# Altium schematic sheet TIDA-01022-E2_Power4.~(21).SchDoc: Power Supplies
size 431 x 279 mm; Date: Not shown in title block; ApprovedBy: Not shown in title block; CheckedBy: Not shown in title block; Author: Not shown in title block; CompanyName: Not shown in title block; DrawnBy: Avinash N; Engineer: Not shown in title block; Organization: Not shown in title block; Address1: Not shown in title block; Address2: Not shown in title block; Address3: Not shown in title block; Address4: Not shown in title block; DocumentNumber: 1; Revision: Use project parameter SCH_Rev; SheetNumber: 24; SheetTotal: 26; PageSetup: Record=PageOptions¦CenterHorizontal=True¦CenterVertical=True¦PrintScale=1.00¦XCorrection=1.00¦YCorrection=1.00¦PrintKind=0¦BorderSize=5000000¦LeftOffset=0¦BottomOffset=0¦Orientation=2¦PaperLength=1000¦PaperWidth=1000¦Scale=100¦PaperSource=15¦PrintQuality=600¦MediaType=1¦DitherType=10¦PaperKind=Letter¦PrintScaleMode=1
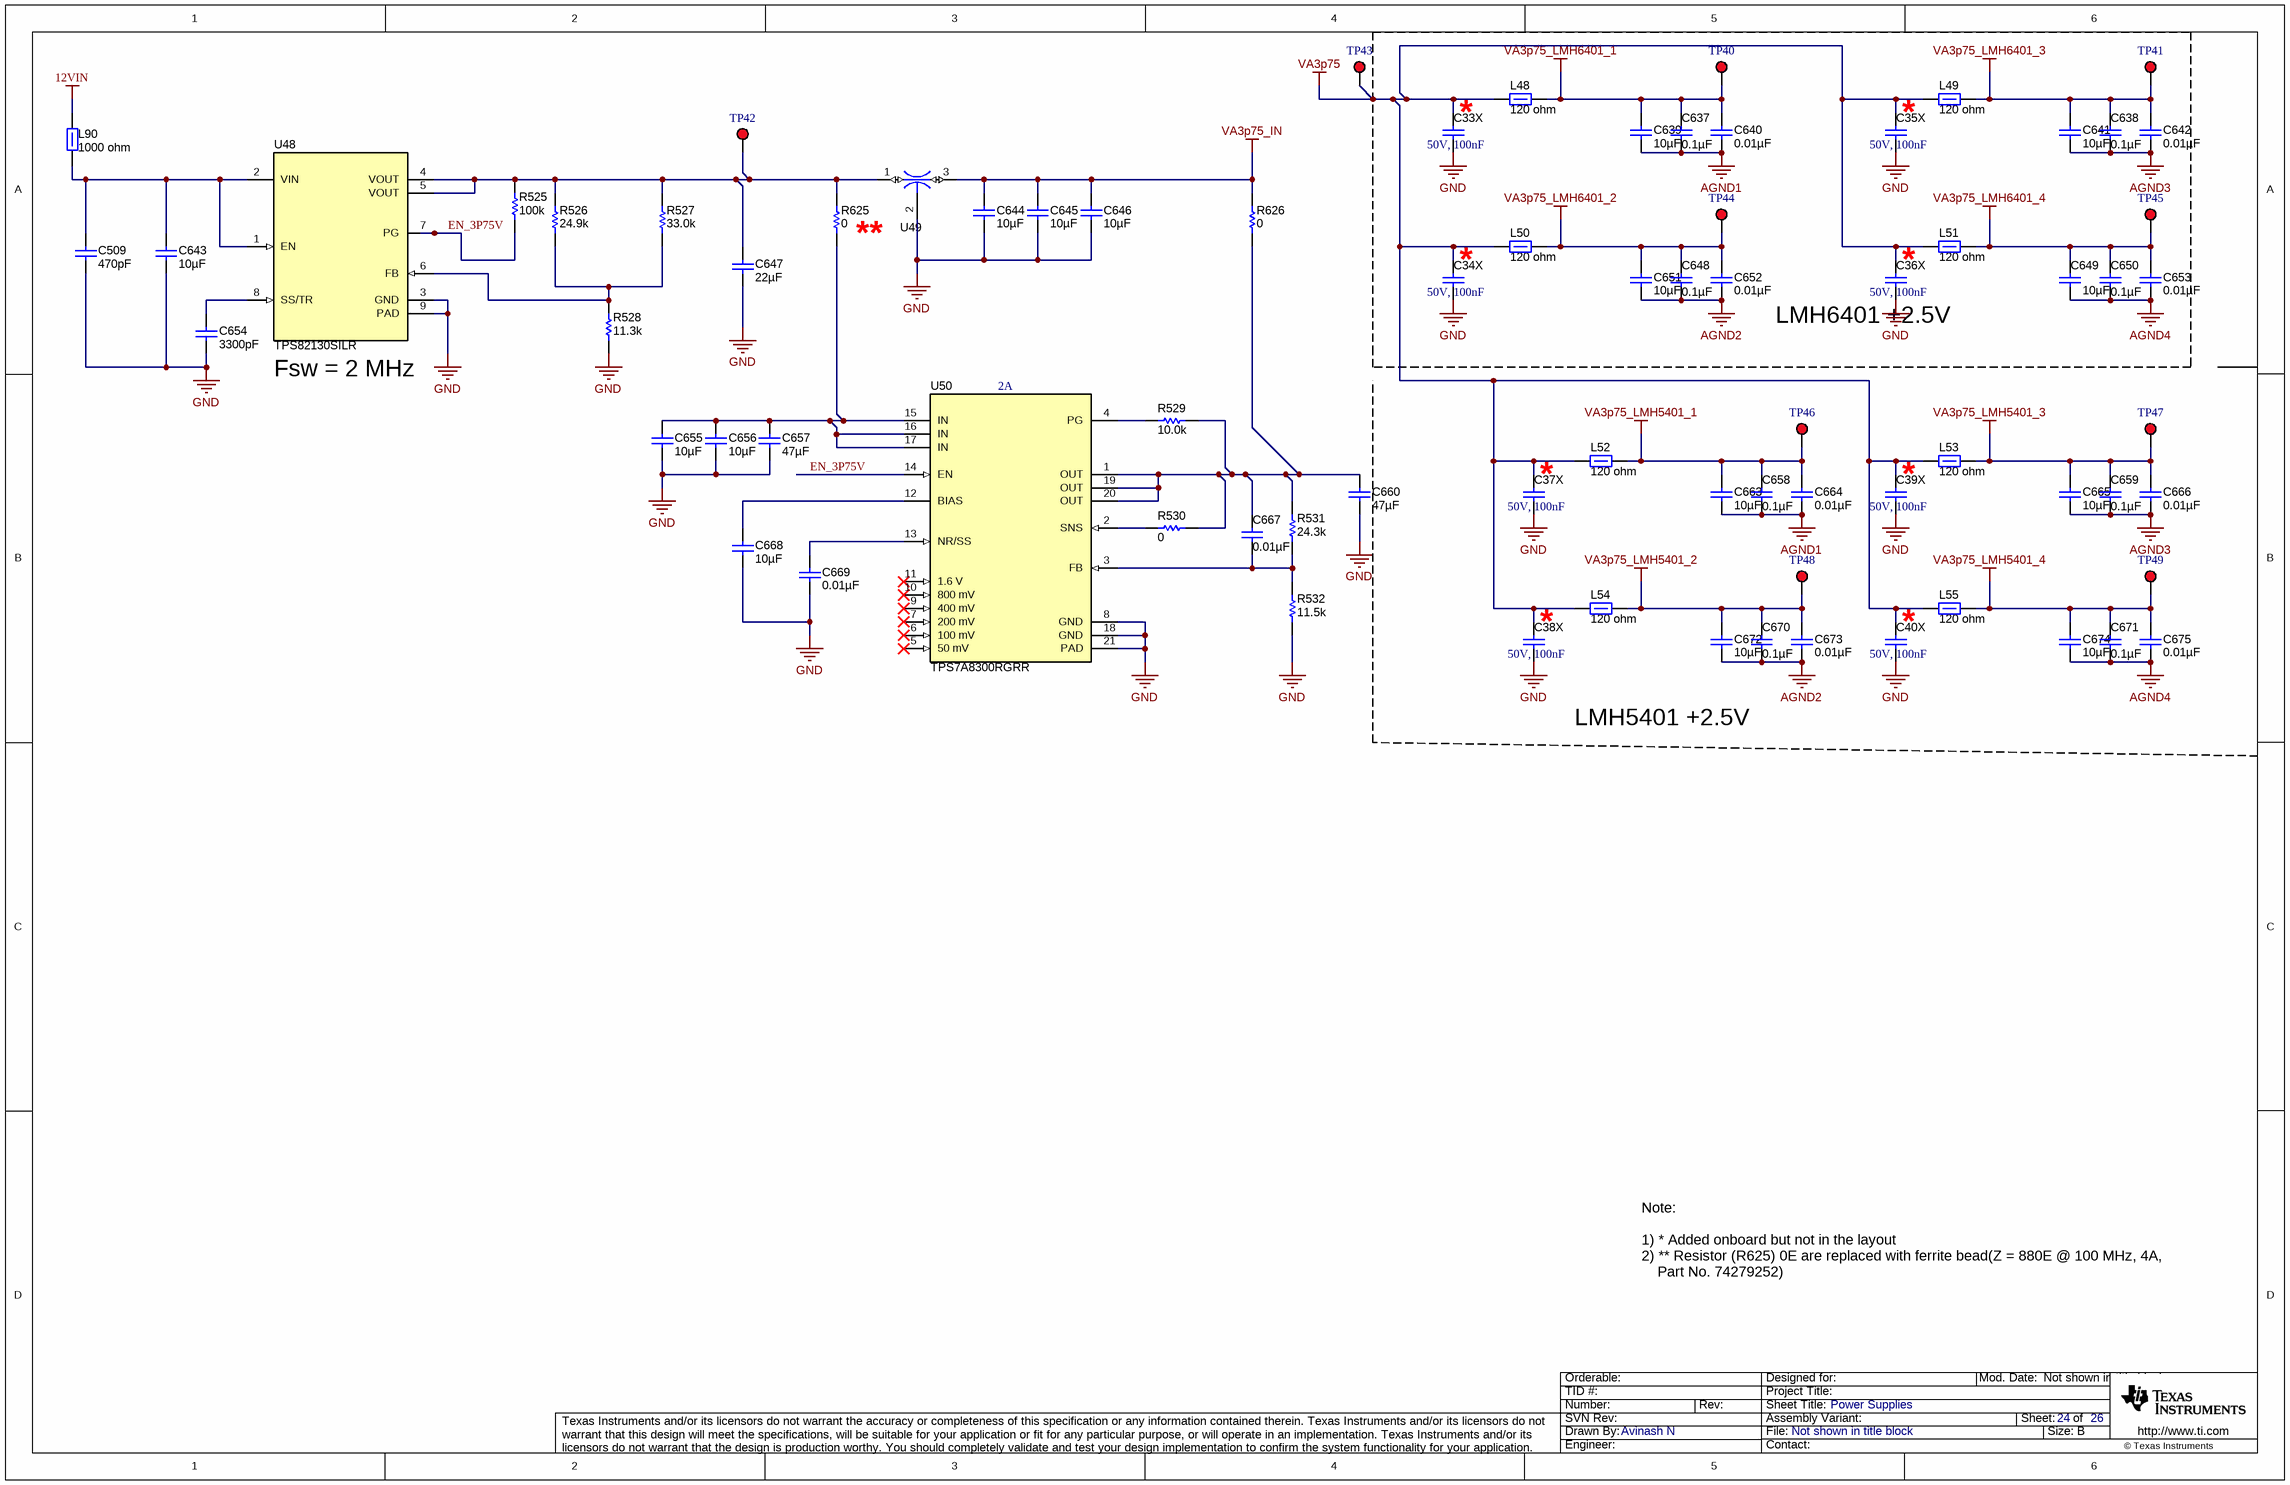
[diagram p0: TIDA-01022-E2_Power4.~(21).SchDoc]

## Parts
C33X  50V, 100nF  [0603_1.6x0.8x0.8mm_Reflow Soldering]
C34X  50V, 100nF  [0603_1.6x0.8x0.8mm_Reflow Soldering]
C35X  50V, 100nF  [0603_1.6x0.8x0.8mm_Reflow Soldering]
C36X  50V, 100nF  [0603_1.6x0.8x0.8mm_Reflow Soldering]
C37X  50V, 100nF  [0603_1.6x0.8x0.8mm_Reflow Soldering]
C38X  50V, 100nF  [0603_1.6x0.8x0.8mm_Reflow Soldering]
C39X  50V, 100nF  [0603_1.6x0.8x0.8mm_Reflow Soldering]
C40X  50V, 100nF  [0603_1.6x0.8x0.8mm_Reflow Soldering]
C509  ValueDisplayed: 470pF  [0402]  (hidden comment: GRM1555C1H471JA01D)
C637  ValueDisplayed: 0.1µF  [0603]  (hidden comment: CGA3E2X7R1H104K080AA)
C638  ValueDisplayed: 0.1µF  [0603]  (hidden comment: CGA3E2X7R1H104K080AA)
C639  ValueDisplayed: 10µF  [1206_190]  (hidden comment: C3216X7R1E106M160AE)
C640  ValueDisplayed: 0.01µF  [0603]  (hidden comment: GCM188R71H103KA37D)
C641  ValueDisplayed: 10µF  [1206_190]  (hidden comment: C3216X7R1E106M160AE)
C642  ValueDisplayed: 0.01µF  [0603]  (hidden comment: GCM188R71H103KA37D)
C643  ValueDisplayed: 10µF  [1206_190]  (hidden comment: C3216X7R1E106M160AE)
C644  ValueDisplayed: 10µF  [1206_190]  (hidden comment: C3216X7R1E106M160AE)
C645  ValueDisplayed: 10µF  [1206_190]  (hidden comment: C3216X7R1E106M160AE)
C646  ValueDisplayed: 10µF  [1206_190]  (hidden comment: C3216X7R1E106M160AE)
C647  ValueDisplayed: 22µF  [0805_HV]  (hidden comment: JMK212BJ226MG-T)
C648  ValueDisplayed: 0.1µF  [0603]  (hidden comment: CGA3E2X7R1H104K080AA)
C649  ValueDisplayed: 10µF  [1206_190]  (hidden comment: C3216X7R1E106M160AE)
C650  ValueDisplayed: 0.1µF  [0603]  (hidden comment: CGA3E2X7R1H104K080AA)
C651  ValueDisplayed: 10µF  [1206_190]  (hidden comment: C3216X7R1E106M160AE)
C652  ValueDisplayed: 0.01µF  [0603]  (hidden comment: GCM188R71H103KA37D)
C653  ValueDisplayed: 0.01µF  [0603]  (hidden comment: GCM188R71H103KA37D)
C654  ValueDisplayed: 3300pF  [0603]  (hidden comment: GRM1885C1H332JA01D)
C655  ValueDisplayed: 10µF  [0805_HV]  (hidden comment: GRM21BR61C106KE15L)
C656  ValueDisplayed: 10µF  [0805_HV]  (hidden comment: GRM21BR61C106KE15L)
C657  ValueDisplayed: 47µF  [0805_HV]  (hidden comment: GRM219R60G476ME44D)
C658  ValueDisplayed: 0.1µF  [0603]  (hidden comment: CGA3E2X7R1H104K080AA)
C659  ValueDisplayed: 0.1µF  [0603]  (hidden comment: CGA3E2X7R1H104K080AA)
C660  ValueDisplayed: 47µF  [0805_HV]  (hidden comment: GRM219R60G476ME44D)
C663  ValueDisplayed: 10µF  [1206_190]  (hidden comment: C3216X7R1E106M160AE)
C664  ValueDisplayed: 0.01µF  [0603]  (hidden comment: GCM188R71H103KA37D)
C665  ValueDisplayed: 10µF  [1206_190]  (hidden comment: C3216X7R1E106M160AE)
C666  ValueDisplayed: 0.01µF  [0603]  (hidden comment: GCM188R71H103KA37D)
C667  ValueDisplayed: 0.01µF  [0603]  (hidden comment: GRM188R71H103KA01D)
C668  ValueDisplayed: 10µF  [0805_HV]  (hidden comment: GRM21BR61C106KE15L)
C669  ValueDisplayed: 0.01µF  [0603]  (hidden comment: GRM188R71H103KA01D)
C670  ValueDisplayed: 0.1µF  [0603]  (hidden comment: CGA3E2X7R1H104K080AA)
C671  ValueDisplayed: 0.1µF  [0603]  (hidden comment: CGA3E2X7R1H104K080AA)
C672  ValueDisplayed: 10µF  [1206_190]  (hidden comment: C3216X7R1E106M160AE)
C673  ValueDisplayed: 0.01µF  [0603]  (hidden comment: GCM188R71H103KA37D)
C674  ValueDisplayed: 10µF  [1206_190]  (hidden comment: C3216X7R1E106M160AE)
C675  ValueDisplayed: 0.01µF  [0603]  (hidden comment: GCM188R71H103KA37D)
L48  ValueDisplayed: 120 ohm  [0603]  (hidden comment: BLM18SG121TN1D)
L49  ValueDisplayed: 120 ohm  [0603]  (hidden comment: BLM18SG121TN1D)
L50  ValueDisplayed: 120 ohm  [0603]  (hidden comment: BLM18SG121TN1D)
L51  ValueDisplayed: 120 ohm  [0603]  (hidden comment: BLM18SG121TN1D)
L52  ValueDisplayed: 120 ohm  [0603]  (hidden comment: BLM18SG121TN1D)
L53  ValueDisplayed: 120 ohm  [0603]  (hidden comment: BLM18SG121TN1D)
L54  ValueDisplayed: 120 ohm  [0603]  (hidden comment: BLM18SG121TN1D)
L55  ValueDisplayed: 120 ohm  [0603]  (hidden comment: BLM18SG121TN1D)
L90  ValueDisplayed: 1000 ohm  [1806_HighSpeed]  (hidden comment: BLM41PG102SN1L)
R525  ValueDisplayed: 100k  [0402]  (hidden comment: CRCW0402100KFKED)
R526  ValueDisplayed: 24.9k  [0603]  (hidden comment: CRCW060324K9FKEA)
R527  ValueDisplayed: 33.0k  [0402]  (hidden comment: ERA-2AEB333X)
R528  ValueDisplayed: 11.3k  [0402]  (hidden comment: CRCW040211K3FKED)
R529  ValueDisplayed: 10.0k  [0603]  (hidden comment: CRCW060310K0FKEA)
R530  ValueDisplayed: 0  [0603]  (hidden comment: CRCW06030000Z0EA)
R531  ValueDisplayed: 24.3k  [0603]  (hidden comment: CRCW060324K3FKEA)
R532  ValueDisplayed: 11.5k  [0603]  (hidden comment: CRCW060311K5FKEA)
R625  ValueDisplayed: 0  [1206]  (hidden comment: CRCW12060000Z0EA)
R626  ValueDisplayed: 0  [1206]  (hidden comment: CRCW12060000Z0EA)
TP40  5000  [Keystone5000]  (value not drawn)
TP41  5000  [Keystone5000]  (value not drawn)
TP42  5000  [Keystone5000]  (value not drawn)
TP43  5000  [Keystone5000]  (value not drawn)
TP44  5000  [Keystone5000]  (value not drawn)
TP45  5000  [Keystone5000]  (value not drawn)
TP46  5000  [Keystone5000]  (value not drawn)
TP47  5000  [Keystone5000]  (value not drawn)
TP48  5000  [Keystone5000]  (value not drawn)
TP49  5000  [Keystone5000]  (value not drawn)
U48  TPS82130SILR  [SIL0008D_SMD]
U49  NFM31PC276B0J3L  [Murata_NFM31P]  (value not drawn)
U50  TPS7A8300RGRR  [RGR0020A]

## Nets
12VIN: L90.2
AGND1: C637.2 C639.1 C640.2 C658.2 C663.1 C664.2
AGND2: C648.2 C651.1 C652.2 C670.2 C672.1 C673.2
AGND3: C638.2 C641.1 C642.2 C659.2 C665.1 C666.2
AGND4: C649.1 C650.2 C653.2 C671.2 C674.1 C675.2
GND: C33X.1 C34X.1 C35X.1 C36X.1 C37X.1 C38X.1 C39X.1 C40X.1 C509.2 C643.2 C644.1 C645.1 C646.1 C647.2 C654.1 C655.2 C656.2 C657.2 C660.2 C668.2 C669.2 R528.1 R532.1 U48.3(GND) U48.9(PAD) U49.2 U50.8(GND) U50.18(GND) U50.21(PAD)
VA3p75: C33X.2 C34X.2 C35X.2 C36X.2 C37X.2 C38X.2 C39X.2 C40X.2 L48.1 L49.1 L50.1 L51.1 L52.1 L53.1 L54.1 L55.1 TP43.1
VA3p75_IN: C644.2 C645.2 C646.2 R626.2 U49.3
VA3p75_LMH5401_1: C658.1 C663.2 C664.1 L52.2 TP46.1
VA3p75_LMH5401_2: C670.1 C672.2 C673.1 L54.2 TP48.1
VA3p75_LMH5401_3: C659.1 C665.2 C666.1 L53.2 TP47.1
VA3p75_LMH5401_4: C671.1 C674.2 C675.1 L55.2 TP49.1
VA3p75_LMH6401_1: C637.1 C639.2 C640.1 L48.2 TP40.1
VA3p75_LMH6401_2: C648.1 C651.2 C652.1 L50.2 TP44.1
VA3p75_LMH6401_3: C638.1 C641.2 C642.1 L49.2 TP41.1
VA3p75_LMH6401_4: C649.2 C650.1 C653.1 L51.2 TP45.1
EN_3P75V: R525.1 U48.7(PG) U50.14(EN)
NetC509_1: C509.1 C643.1 L90.1 U48.1(EN) U48.2(VIN)
NetC647_1: C647.1 R525.2 R526.2 R527.2 R625.2 TP42.1 U48.4(VOUT) U48.5(VOUT) U49.1
NetC654_2: C654.2 U48.8(SS/TR)
NetC655_1: C655.1 C656.1 C657.1 R625.1 U50.15(IN) U50.16(IN) U50.17(IN)
NetC660_1: C660.1 C667.1 R529.1 R530.2 R531.2 R626.1 U50.1(OUT) U50.19(OUT) U50.20(OUT)
NetC667_2: C667.2 R531.1 R532.2 U50.3(FB)
NetC668_1: C668.1 U50.12(BIAS)
NetC669_1: C669.1 U50.13(NR/SS)
NetR526_1: R526.1 R527.1 R528.2 U48.6(FB)
NetR529_2: R529.2 U50.4(PG)
NetR530_1: R530.1 U50.2(SNS)

Not connected (* = marked no-connect by the designer): U50 5(50_mV)* 6(100_mV)* 7(200_mV)* 9(400_mV)* 10(800_mV)* 11(1.6_V)*

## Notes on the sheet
- (near C33X) *
- (near C35X) *
- (near R625) *
- *
- (near C34X) *
- (near C36X) *
- (near C36X) LMH6401 +2.5V
- (near U48) Fsw = 2 MHz
- (near U50) 2A
- (near C37X) *
- (near C39X) *
- (near C38X) *
- (near C40X) *
- LMH5401 +2.5V
- Note:
  1) * Added onboard but not in the layout
  2) ** Resistor (R625) 0E are replaced with ferrite bead(Z = 880E @ 100 MHz, 4A,
  Part No. 74279252)

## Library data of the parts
C33X C34X C35X C36X C37X C38X C39X C40X = 885012206095: WCAP-CSGP Ceramic Capacitors, 0603, X7R, 50V, 100nF; Rated Voltage: 50V DC
C509 = GRM1555C1H471JA01D: CAP, CERM, 470 pF, 50 V, +/- 5%, C0G/NP0, 0402; Manufacturer: MuRata; Polarized: N; CompType: Capacitor; Value: 470pF; U/M: EA; Cap_F: 0.00000000047; Tolerance_%: 5; Value1: Unknown; VDC_V: 50; Value2: 50V; TaMin_C: -55; TaMax_C: 125; SizeArea_mm2: 0.5; SizeAreaWB_mm2: 3; SizeX_mm: 1; SizeZ_mm: 0.6; AEC Category: Q200
C637 C638 C648 C650 C658 C659 C670 C671 = CGA3E2X7R1H104K080AA: CAP, CERM, 0.1 µF, 50 V, +/- 10%, X7R, AEC-Q200 Grade 1, 0603; Manufacturer: TDK; Polarized: N; CompType: Capacitor; Value: 0.1uF; U/M: EA; Cap_F: 0.0000001; Tolerance_%: 10; ESR_ohm: 0.0296; Value1: 0.0296 ohm; VDC_V: 50; Value2: 50V; IRMS_A: 0.97199; TaMin_C: -55; TaMax_C: 125; SizeArea_mm2: 1.28; SizeAreaWB_mm2: 4.68; SizeX_mm: 1.6; SizeY_mm: 0.8; SizeZ_mm: 1; AEC Category: Q200; AEC Qualified: Y
C639 C641 C643-C646 C649 C651 C663 C665 C672 C674 = C3216X7R1E106M160AE: CAP, CERM, 10 µF, 25 V, +/- 20%, X7R, 1206_190; Manufacturer: TDK; Polarized: N; CompType: Capacitor; Value: 10uF; U/M: EA; Cap_F: 0.00001; Tolerance_%: 20; Value1: Unknown; VDC_V: 25; Value2: 25V; TaMin_C: -55; TaMax_C: 125; Cap_Case: 1206; SizeArea_mm2: 5.12; SizeAreaWB_mm2: 10.92; SizeX_mm: 3.2; SizeY_mm: 1.6; SizeZ_mm: 1.9; AEC Category: Q200
C640 C642 C652 C653 C664 C666 C673 C675 = GCM188R71H103KA37D: CAP, CERM, 0.01 µF, 50 V, +/- 10%, X7R, AEC-Q200 Grade 1, 0603; Manufacturer: MuRata; Polarized: N; CompType: Capacitor; Value: 0.01uF; U/M: EA; Cap_F: 0.00000001; Tolerance_%: 10; Value1: Unknown; VDC_V: 50; Value2: 50V; TaMin_C: -55; TaMax_C: 125; SizeArea_mm2: 1.28; SizeAreaWB_mm2: 4.68; SizeX_mm: 1.6; SizeY_mm: 0.8; SizeZ_mm: 1; AEC Category: Q200; AEC Qualified: Y
C647 = JMK212BJ226MG-T: CAP, CERM, 22 µF, 6.3 V, +/- 20%, X5R, 0805; Manufacturer: Taiyo Yuden; Polarized: N; CompType: Capacitor; Value: 22uF; U/M: EA; Cap_F: 0.000022; Tolerance_%: 20; Value1: Unknown; VDC_V: 6.3; Value2: 6.3V; TaMin_C: -55; TaMax_C: 85; Cap_Case: 0805; SizeArea_mm2: 2.5; SizeAreaWB_mm2: 6.75; SizeX_mm: 2; SizeY_mm: 1.25; SizeZ_mm: 1.45; AEC Category: Q200
C654 = GRM1885C1H332JA01D: CAP, CERM, 3300 pF, 50 V, +/- 5%, C0G/NP0, 0603; Manufacturer: MuRata; Polarized: N; CompType: Capacitor; Value: 3300pF; U/M: EA; Cap_F: 0.0000000033; Tolerance_%: 5; Value1: Unknown; VDC_V: 50; Value2: 50V; TaMin_C: -55; TaMax_C: 125; SizeArea_mm2: 1.28; SizeAreaWB_mm2: 4.68; SizeX_mm: 1.6; SizeY_mm: 0.8; SizeZ_mm: 1; AEC Category: Q200
C655 C656 C668 = GRM21BR61C106KE15L: CAP, CERM, 10 µF, 16 V, +/- 10%, X5R, 0805; Manufacturer: MuRata; Polarized: N; CompType: Capacitor; Value: 10uF; U/M: EA; Cap_F: 0.00001; Tolerance_%: 10; ESR_ohm: 0.008; Value1: 0.008 ohm; VDC_V: 16; Value2: 16V; TaMin_C: -55; TaMax_C: 85; Cap_Case: 0805; SizeArea_mm2: 2.5; SizeAreaWB_mm2: 6.75; SizeX_mm: 2; SizeY_mm: 1.25; SizeZ_mm: 1.45; AEC Category: Q200
C657 C660 = GRM219R60G476ME44D: CAP, CERM, 47 µF, 4 V, +/- 20%, X5R, 0805; Manufacturer: MuRata; Polarized: N; CompType: Capacitor; Value: 47uF; U/M: EA; Cap_F: 0.000047; Tolerance_%: 20; Value1: Unknown; VDC_V: 4; Value2: 4V; TaMin_C: -55; TaMax_C: 85; Cap_Case: 0805; SizeArea_mm2: 2.5; SizeAreaWB_mm2: 6.75; SizeX_mm: 2; SizeY_mm: 1.25; SizeZ_mm: 1.45; AEC Category: Q200
C667 C669 = GRM188R71H103KA01D: CAP, CERM, 0.01 µF, 50 V, +/- 10%, X7R, 0603; Manufacturer: MuRata; Polarized: N; CompType: Capacitor; Value: 0.01uF; U/M: EA; Cap_F: 0.00000001; Tolerance_%: 10; Value1: Unknown; VDC_V: 50; Value2: 50V; TaMin_C: -55; TaMax_C: 125; SizeArea_mm2: 1.28; SizeAreaWB_mm2: 4.68; SizeX_mm: 1.6; SizeY_mm: 0.8; SizeZ_mm: 1; AEC Category: Q200
L48-L55 = BLM18SG121TN1D: Ferrite Bead, 120 ohm @ 100 MHz, 3 A, 0603; Manufacturer: MuRata; Value: 120 ohm; Imax_A: 3; DCR_ohm: 0.025; Value1: 0.025 ohm; Value2: 3A; SizeAreaWB_mm2: 4.68; SizeArea_mm2: 1.28; SizeX_mm: 1.6; SizeY_mm: 0.8; SizeZ_mm: 1; ZTyp@100MHz_Ohm: 120
L90 = BLM41PG102SN1L: Ferrite Bead, 1000 ohm @ 100 MHz, 1.5 A, 1806; Manufacturer: MuRata; Imax_A: 1.5; DCR_ohm: 0.09; Value1: 0.09 ohm; Value2: 1.5A; SizeAreaWB_mm2: 14.3; SizeArea_mm2: 7.2; SizeX_mm: 4.5; SizeY_mm: 1.6; SizeZ_mm: 1.85; ZTyp@100MHz_Ohm: 1000
R525 = CRCW0402100KFKED: RES, 100 k, 1%, 0.063 W, 0402; Manufacturer: Vishay-Dale; CompType: Resistor; Value: 100k; Res_ohm: 100000; Tolerance_%: 1; Power_W: 0.063; Value2: 0.063W; VDC_V: 50; TempCo: 100 ppm/C; SizeArea_mm2: 0.5; SizeZ_mm: 0.6; EIA_Code: E96; U/M: EA; AEC Category: Q200
R526 = CRCW060324K9FKEA: RES, 24.9 k, 1%, 0.1 W, 0603; Manufacturer: Vishay-Dale; CompType: Resistor; Value: 24.9k; Res_ohm: 24900; Value_Code: 24k9; Tolerance_%: 1; Power_W: 0.1; Value2: 0.1W; VDC_V: 75; TempCo: 100 ppm/C; SizeArea_mm2: 1.28; SizeX_mm: 1.6; SizeY_mm: 0.8; EIA_Code: E96; U/M: EA; AEC Category: Q200
R527 = ERA-2AEB333X: RES, 33.0 k, 0.1%, 0.063 W, 0402; Manufacturer: Panasonic; CompType: Resistor; Value: 33.0k; Res_ohm: 33000; Value_Code: 33k0; Tolerance_%: 0.1; Power_W: 0.063; Value2: 0.063W; VDC_V: 50; TempCo: 25 ppm/C; SizeArea_mm2: 0.5; SizeX_mm: 1; SizeZ_mm: 0.6; U/M: EA; AEC Category: Q200
R528 = CRCW040211K3FKED: RES, 11.3 k, 1%, 0.063 W, 0402; Manufacturer: Vishay-Dale; CompType: Resistor; Value: 11.3k; Res_ohm: 11300; Value_Code: 11k3; Tolerance_%: 1; Power_W: 0.063; Value2: 0.063W; VDC_V: 50; TempCo: 100 ppm/C; SizeArea_mm2: 0.5; SizeZ_mm: 0.6; EIA_Code: E96; U/M: EA; AEC Category: Q200
R529 = CRCW060310K0FKEA: RES, 10.0 k, 1%, 0.1 W, 0603; Manufacturer: Vishay-Dale; CompType: Resistor; Value: 10.0k; Res_ohm: 10000; Value_Code: 10k0; Tolerance_%: 1; Power_W: 0.1; Value2: 0.1W; VDC_V: 75; TempCo: 100 ppm/C; SizeArea_mm2: 1.28; SizeX_mm: 1.6; SizeY_mm: 0.8; EIA_Code: E96; U/M: EA; AEC Category: Q200
R530 = CRCW06030000Z0EA: RES, 0, 5%, 0.1 W, 0603; Manufacturer: Vishay-Dale; CompType: Resistor; Value: 0; Value_Code: 0000; Tolerance_%: 5; Power_W: 0.1; Value2: 0.1W; VDC_V: 75; TempCo: 200 ppm/C; SizeArea_mm2: 1.28; SizeX_mm: 1.6; SizeY_mm: 0.8; SizeZ_mm: 1; EIA_Code: E24; U/M: EA; AEC Category: Q200
R531 = CRCW060324K3FKEA: RES, 24.3 k, 1%, 0.1 W, 0603; Manufacturer: Vishay-Dale; CompType: Resistor; Value: 24.3k; Res_ohm: 24300; Value_Code: 24k3; Tolerance_%: 1; Power_W: 0.1; Value2: 0.1W; VDC_V: 75; TempCo: 100 ppm/C; SizeArea_mm2: 1.28; SizeX_mm: 1.6; SizeY_mm: 0.8; EIA_Code: E96; U/M: EA; AEC Category: Q200
R532 = CRCW060311K5FKEA: RES, 11.5 k, 1%, 0.1 W, 0603; Manufacturer: Vishay-Dale; CompType: Resistor; Value: 11.5k; Res_ohm: 11500; Value_Code: 11k5; Tolerance_%: 1; Power_W: 0.1; Value2: 0.1W; VDC_V: 75; TempCo: 100 ppm/C; SizeArea_mm2: 1.28; SizeX_mm: 1.6; SizeY_mm: 0.8; EIA_Code: E96; U/M: EA; AEC Category: Q200
R625 R626 = CRCW12060000Z0EA: RES, 0, 5%, 0.25 W, 1206; Manufacturer: Vishay-Dale; CompType: Resistor; Value: 0; Value_Code: 0000; Tolerance_%: 5; Power_W: 0.25; Value2: 0.25W; VDC_V: 200; TempCo: 200 ppm/C; SizeArea_mm2: 5.12; SizeX_mm: 3.2; SizeY_mm: 1.6; SizeZ_mm: 1.35; EIA_Code: E24; U/M: EA; AEC Category: Q200
TP40-TP49 = 5000: Test Point, Miniature, Red, TH; Manufacturer: Keystone; CompType: Test Point Loop; ContactFinish: Silver; Green_Lifecycle: Active; Green_REACh: Passed
U48 = TPS82130SILR: 3-A 17V Step-down Converter Module with Integrated Inductor, SIL0008D (uSIP-8); Alternate PartNumber: TPS82130SILT; Manufacturer: Texas Instruments; SymbolCreator: Altium; SizeArea_mm2: 12.25; SizeAreaWB_mm2: 20.25; SizeX_mm: 3.5; SizeZ_mm: 1.53; CompType: IC; U/M: EA
U49 = NFM31PC276B0J3L: FILTER LC HIGH FREQ 27uF 1206; Manufacturer: MuRata; SymbolCreator: Altium
U50 = TPS7A8300RGRR: 2A, Low-Dropout Voltage Regulator for High Speed Communication Systems, RGR0020A (VQFN-20); Alternate PartNumber: TPS7A8300RGRT; Manufacturer: Texas Instruments; SymbolCreator: a0411947; SizeArea_mm2: 12.25; SizeAreaWB_mm2: 20.25; SizeX_mm: 3.5; SizeZ_mm: 1; CompType: IC; U/M: EA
